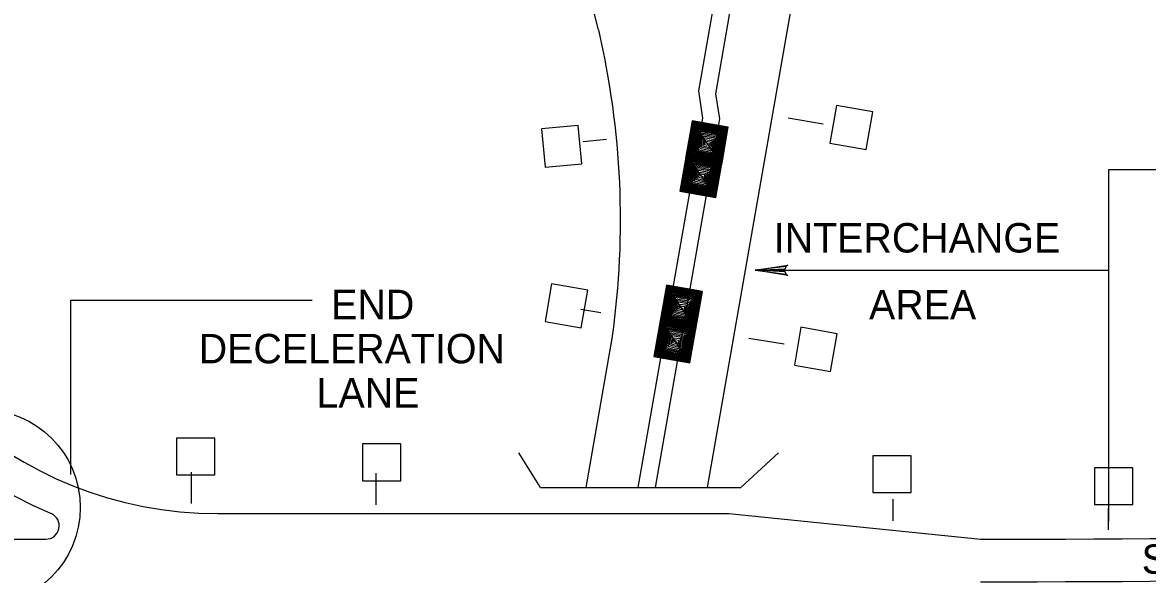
# Model space of a CAD drawing. Extents: x 640253 to 641999, y 298458 to 299646.
# Drawn here: x 641521.2 to 641635.9, y 299419 to 299475.2 of the extents above; entities that cross this region are included whole.
import ezdxf

# ---------------------------------------------------------------- set-up
doc = ezdxf.new("R2010")
doc.units = 0
doc.layers.add('2', color=7, linetype='Continuous')

msp = doc.modelspace()

# ---------------------------------------------------------------- linework, layer by layer
at = {"layer": '2'}
for p, q in [((641591, 299427.89), (641610.58, 299539.79)), ((641590.13, 299468.28), (641594.87, 299495.41)), ((641591.85, 299467.98), (641596.59, 299495.11)), ((641590.55, 299465.5), (641590.13, 299468.28)), ((641592.28, 299465.43), (641591.85, 299467.98)), ((641583.95, 299427.89), (641590.55, 299465.5)), ((641585.72, 299427.89), (641592.28, 299465.43)), ((641599.23, 299465.53), (641602.82, 299464.94)), ((641580.72, 299463.33), (641578.35, 299463.09)), ((641588.79, 299461.56), (641592.39, 299460.97)), ((641631.93, 299424.45), (641631.93, 299460.29)), ((641631.93, 299460.29), (641646.8, 299460.29)), ((641595.89, 299450.02), (641631.93, 299450.02)), ((641526.12, 299429.21), (641526.12, 299446.98)), ((641526.12, 299446.98), (641550.71, 299446.98)), ((641580.15, 299445.68), (641578.1, 299446.02)), ((641586.23, 299444.88), (641589.82, 299444.29)), ((641578.64, 299427.89), (641581.33, 299443.28)), ((641581.33, 299443.28), (641581.33, 299443.28)), ((641595.23, 299443.11), (641598.83, 299442.52)), ((641574.01, 299427.89), (641571.77, 299431.41)), ((641594.4, 299427.89), (641598.24, 299431.41)), ((641538.42, 299426.26), (641538.42, 299429.45)), ((641557.24, 299426.13), (641557.24, 299429.33)), ((641574.01, 299427.89), (641594.4, 299427.89)), ((641609.94, 299424.48), (641609.94, 299426.69)), ((641541.11, 299425.23), (641541.11, 299425.23)), ((641541.11, 299425.23), (641593.19, 299425.23)), ((641593.19, 299425.23), (641618.86, 299422.63)), ((641593.19, 299425.23), (641593.19, 299425.23)), ((641631.89, 299423.56), (641631.89, 299425.77)), ((641394.9, 299422.63), (641523.58, 299422.63))]:
    msp.add_line(p, q, dxfattribs=at)
for points in [[(641607.19, 299462.32), (641607.86, 299466.16), (641604.17, 299466.8), (641603.5, 299462.96)], [(641578.19, 299460.86), (641577.84, 299464.75), (641574.11, 299464.41), (641574.46, 299460.53)], [(641578.15, 299444.15), (641578.82, 299447.99), (641575.13, 299448.64), (641574.46, 299444.8)], [(641603.56, 299439.71), (641604.23, 299443.55), (641600.54, 299444.2), (641599.87, 299440.36)], [(641536.89, 299429.18), (641540.79, 299429.18), (641540.79, 299432.92), (641536.89, 299432.92)], [(641555.85, 299428.57), (641559.75, 299428.57), (641559.75, 299432.32), (641555.85, 299432.32)], [(641607.88, 299427.36), (641611.78, 299427.36), (641611.78, 299431.11), (641607.88, 299431.11)], [(641630.46, 299426.15), (641634.36, 299426.15), (641634.36, 299429.9), (641630.46, 299429.9)]]:
    msp.add_lwpolyline(points, close=True, dxfattribs=at)
for points in [[(641592.46, 299460.76), (641593.13, 299464.6), (641589.44, 299465.25), (641588.77, 299461.41), (641592.46, 299460.76), (641589.5, 299465.17), (641588.85, 299461.46), (641592.42, 299460.83), (641593.07, 299464.55), (641589.56, 299465.16), (641588.93, 299461.52), (641592.36, 299460.92), (641592.99, 299464.48), (641589.64, 299465.06), (641589.03, 299461.57), (641592.32, 299461), (641592.92, 299464.43), (641589.68, 299464.99), (641589.1, 299461.63), (641592.27, 299461.08), (641592.84, 299464.36), (641589.74, 299464.9), (641589.18, 299461.69), (641592.23, 299461.14), (641592.76, 299464.31), (641589.8, 299464.81), (641589.26, 299461.74), (641592.17, 299461.22), (641592.68, 299464.25), (641589.85, 299464.73), (641589.34, 299461.8), (641592.1, 299461.3), (641592.59, 299464.18), (641589.93, 299464.64), (641589.43, 299461.87), (641592.07, 299461.37), (641592.5, 299464.1), (641589.97, 299464.55), (641589.51, 299461.93), (641592.01, 299461.46), (641592.43, 299464.03), (641590.01, 299464.45), (641589.6, 299462), (641591.99, 299461.54), (641592.34, 299463.95), (641590.07, 299464.34), (641589.71, 299462.07), (641590.78, 299461.83), (641591.94, 299461.63), (641592.25, 299463.89), (641590.15, 299464.23), (641589.83, 299462.13), (641591.88, 299461.73), (641592.17, 299463.82), (641590.21, 299464.13), (641589.94, 299462.22), (641591.81, 299461.85), (641592.08, 299463.7), (641590.32, 299463.99), (641590.07, 299462.33), (641591.7, 299461.99), (641591.95, 299463.58), (641590.4, 299463.83), (641590.22, 299462.46), (641591.61, 299462.15), (641591.61, 299462.15), (641591.79, 299463.46), (641590.52, 299463.67), (641590.37, 299462.58), (641591.51, 299462.31), (641591.63, 299463.33), (641590.65, 299463.51), (641590.53, 299462.69), (641591.39, 299462.5), (641591.48, 299463.2), (641590.74, 299463.3), (641590.69, 299462.83), (641591.28, 299462.71), (641591.31, 299463.05), (641590.87, 299463.12), (641590.82, 299462.98), (641591.17, 299462.9)], [(641591.88, 299457.43), (641592.55, 299461.27), (641588.86, 299461.92), (641588.19, 299458.07), (641591.88, 299457.43), (641588.91, 299461.84), (641588.27, 299458.13), (641591.84, 299457.5), (641592.49, 299461.22), (641588.98, 299461.83), (641588.34, 299458.19), (641591.78, 299457.59), (641592.41, 299461.15), (641589.05, 299461.73), (641588.44, 299458.24), (641591.74, 299457.67), (641592.34, 299461.1), (641589.1, 299461.66), (641588.51, 299458.3), (641591.69, 299457.75), (641592.26, 299461.03), (641589.15, 299461.56), (641588.59, 299458.36), (641591.64, 299457.81), (641592.18, 299460.98), (641589.21, 299461.47), (641588.68, 299458.41), (641591.59, 299457.89), (641592.1, 299460.92), (641589.27, 299461.4), (641588.76, 299458.47), (641591.52, 299457.96), (641592.01, 299460.85), (641589.35, 299461.31), (641588.85, 299458.54), (641591.49, 299458.04), (641591.91, 299460.76), (641589.39, 299461.21), (641588.93, 299458.6), (641591.43, 299458.13), (641591.84, 299460.7), (641589.43, 299461.12), (641589.02, 299458.67), (641591.41, 299458.21), (641591.76, 299460.62), (641589.49, 299461.01), (641589.12, 299458.74), (641590.2, 299458.5), (641591.35, 299458.3), (641591.67, 299460.56), (641589.57, 299460.9), (641589.24, 299458.8), (641591.29, 299458.4), (641591.59, 299460.48), (641589.63, 299460.8), (641589.36, 299458.88), (641591.22, 299458.52), (641591.5, 299460.37), (641589.74, 299460.66), (641589.49, 299459), (641591.12, 299458.66), (641591.37, 299460.25), (641589.82, 299460.5), (641589.64, 299459.13), (641591.03, 299458.81), (641591.03, 299458.82), (641591.21, 299460.13), (641589.94, 299460.34), (641589.79, 299459.25), (641590.93, 299458.98), (641591.04, 299460), (641590.07, 299460.18), (641589.94, 299459.36), (641590.8, 299459.17), (641590.89, 299459.86), (641590.16, 299459.96), (641590.11, 299459.5), (641590.7, 299459.37), (641590.73, 299459.72), (641590.29, 299459.79), (641590.23, 299459.65), (641590.58, 299459.57)], [(641599.05, 299449.62), (641598.93, 299449.84), (641595.89, 299450.02), (641599.05, 299449.62), (641599.21, 299449.48), (641595.89, 299450.02), (641598.93, 299450.17), (641599.04, 299450.4), (641595.89, 299450.02), (641599.21, 299450.54), (641599.04, 299450.4)], [(641589.84, 299444.01), (641590.51, 299447.85), (641586.82, 299448.5), (641586.15, 299444.65), (641589.84, 299444.01), (641586.87, 299448.42), (641586.23, 299444.71), (641589.8, 299444.08), (641590.45, 299447.8), (641586.94, 299448.41), (641586.3, 299444.77), (641589.74, 299444.17), (641590.36, 299447.73), (641587.01, 299448.31), (641586.4, 299444.82), (641589.7, 299444.25), (641590.3, 299447.68), (641587.06, 299448.24), (641586.47, 299444.88), (641589.65, 299444.32), (641590.22, 299447.61), (641587.11, 299448.14), (641586.55, 299444.94), (641589.6, 299444.39), (641590.14, 299447.56), (641587.17, 299448.05), (641586.64, 299444.99), (641589.55, 299444.47), (641590.06, 299447.5), (641587.23, 299447.97), (641586.72, 299445.05), (641589.48, 299444.54), (641589.96, 299447.43), (641587.31, 299447.89), (641586.81, 299445.12), (641589.45, 299444.62), (641589.87, 299447.34), (641587.35, 299447.79), (641586.89, 299445.18), (641589.39, 299444.71), (641589.8, 299447.28), (641587.39, 299447.7), (641586.98, 299445.25), (641589.37, 299444.79), (641589.72, 299447.2), (641587.45, 299447.59), (641587.08, 299445.32), (641588.16, 299445.08), (641589.31, 299444.88), (641589.63, 299447.14), (641587.53, 299447.48), (641587.2, 299445.38), (641589.25, 299444.98), (641589.55, 299447.06), (641587.59, 299447.38), (641587.32, 299445.46), (641589.18, 299445.1), (641589.46, 299446.95), (641587.7, 299447.24), (641587.45, 299445.58), (641589.08, 299445.24), (641589.33, 299446.83), (641587.78, 299447.08), (641587.6, 299445.71), (641588.99, 299445.39), (641588.99, 299445.4), (641589.17, 299446.71), (641587.9, 299446.92), (641587.75, 299445.82), (641588.89, 299445.56), (641589, 299446.58), (641588.03, 299446.76), (641587.9, 299445.94), (641588.76, 299445.75), (641588.85, 299446.44), (641588.12, 299446.54), (641588.07, 299446.08), (641588.66, 299445.95), (641588.69, 299446.3), (641588.25, 299446.37), (641588.19, 299446.23), (641588.54, 299446.15)], [(641589.23, 299440.58), (641589.9, 299444.42), (641586.21, 299445.07), (641585.54, 299441.22), (641589.23, 299440.58), (641586.27, 299444.99), (641585.62, 299441.28), (641589.19, 299440.65), (641589.84, 299444.37), (641586.34, 299444.98), (641585.7, 299441.34), (641589.14, 299440.74), (641589.76, 299444.3), (641586.41, 299444.88), (641585.8, 299441.39), (641589.09, 299440.82), (641589.69, 299444.25), (641586.46, 299444.81), (641585.87, 299441.45), (641589.05, 299440.9), (641589.61, 299444.18), (641586.51, 299444.71), (641585.95, 299441.51), (641589, 299440.96), (641589.53, 299444.13), (641586.57, 299444.62), (641586.03, 299441.56), (641588.95, 299441.04), (641589.45, 299444.07), (641586.63, 299444.55), (641586.11, 299441.62), (641588.88, 299441.11), (641589.36, 299444), (641586.7, 299444.46), (641586.21, 299441.69), (641588.84, 299441.19), (641589.27, 299443.91), (641586.74, 299444.36), (641586.29, 299441.75), (641588.79, 299441.28), (641589.2, 299443.85), (641586.79, 299444.27), (641586.38, 299441.82), (641588.76, 299441.36), (641589.11, 299443.77), (641586.85, 299444.16), (641586.48, 299441.89), (641587.55, 299441.65), (641588.71, 299441.45), (641589.03, 299443.71), (641586.93, 299444.05), (641586.6, 299441.95), (641588.65, 299441.55), (641588.94, 299443.63), (641586.99, 299443.95), (641586.71, 299442.03), (641588.58, 299441.67), (641588.85, 299443.52), (641587.09, 299443.81), (641586.84, 299442.15), (641588.48, 299441.81), (641588.72, 299443.4), (641587.17, 299443.65), (641586.99, 299442.28), (641588.38, 299441.96), (641588.39, 299441.97), (641588.56, 299443.28), (641587.29, 299443.49), (641587.14, 299442.4), (641588.28, 299442.13), (641588.4, 299443.15), (641587.42, 299443.33), (641587.3, 299442.51), (641588.16, 299442.32), (641588.25, 299443.01), (641587.51, 299443.11), (641587.46, 299442.65), (641588.05, 299442.52), (641588.08, 299442.87), (641587.64, 299442.94), (641587.59, 299442.8), (641587.94, 299442.72)]]:
    msp.add_lwpolyline(points, dxfattribs=at)
msp.add_circle((641517.08, 299425.85), 10, dxfattribs=at)
for centre, radius, start, end in [((641541.11, 299465.15), 43.39, 80.0478, 246.9218), ((641541.11, 299465.15), 39.92, 13.5395, 270), ((641496.48, 299455.1), 85.67, 352.0739, 13.0849), ((641618.76, 301866.5), 2443.88, 270.0023, 274.32557), ((641523.58, 299423.98), 1.36, 270, 66.9261), ((641618.76, 301866.5), 2448.22, 270.0023, 274.31789)]:
    msp.add_arc(centre, radius, start, end, dxfattribs=at)

# ---------------------------------------------------------------- texts
for s, p in [('INTERCHANGE', (641597.77, 299451.82)), ('END', (641552.66, 299445.03)), ('AREA', (641607.48, 299445)), ('DECELERATION', (641539.16, 299440.53)), ('LANE', (641551.17, 299436.03))]:
    msp.add_text(s, height=3, dxfattribs=at).set_placement(p)
msp.add_text('SOUTHBOUND', height=3, rotation=0.7104, dxfattribs=at).set_placement((641635.29, 299419.08))

doc.saveas('drawing.dxf')
